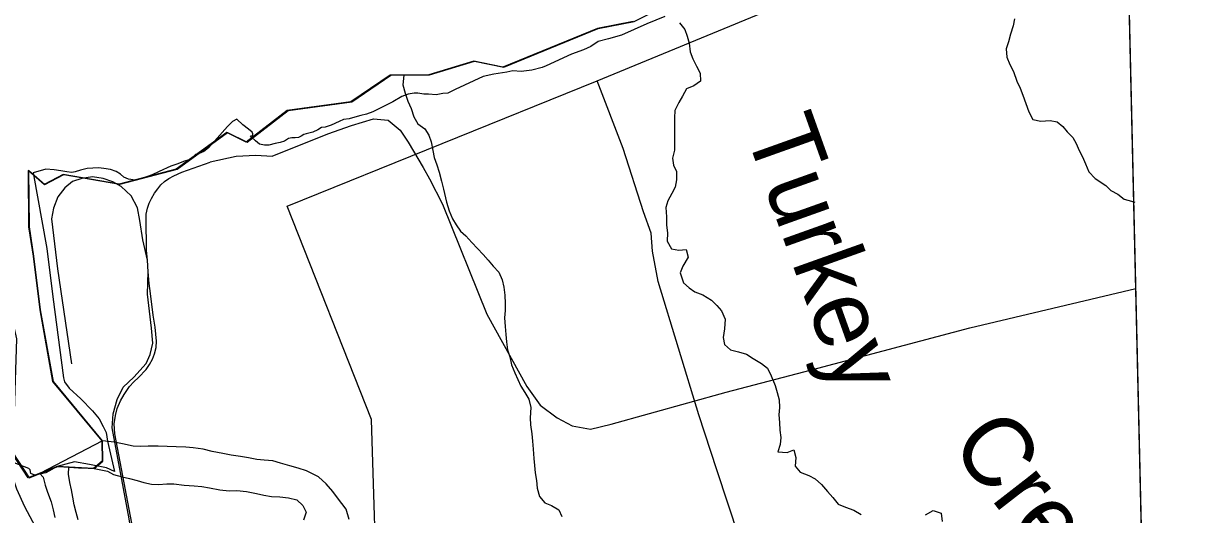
# Model space of a CAD drawing. Extents: x -5.4 to 71.3, y -12 to 22.
# Drawn here: x 5.375 to 6.976, y 17.692 to 18.359 of the extents above; entities that cross this region are included whole.
import ezdxf

# ---------------------------------------------------------------- set-up
doc = ezdxf.new("R2010")
doc.units = 0
for name, color, linetype in [('GM_X_City_Street', 7, 'Continuous'), ('GM_X_Major_Lake', 7, 'Continuous'), ('GM_X_Minor_River', 7, 'Continuous'), ('GM_X_Minor_River_Text', 7, 'Continuous'), ('GM_X_Rail_Line', 7, 'Continuous'), ('PM_X_Surveyed_Line', 7, 'Continuous'), ('SH_Cut_Line', 7, 'Continuous')]:
    doc.layers.add(name, color=color, linetype=linetype)

msp = doc.modelspace()

# ---------------------------------------------------------------- linework, layer by layer
at = {"layer": 'GM_X_City_Street'}
for points in [[(5.7326, 18.1109), (6.1537, 18.2812), (6.3856, 18.3767), (6.6338, 18.4748), (6.7914, 18.529), (6.8726, 18.5488)], [(6.407, 16.3093), (6.397, 16.5818), (6.3923, 16.6844), (6.3863, 16.833), (6.3845, 16.926), (6.3806, 16.9764), (6.3788, 17.0696), (6.3745, 17.1827), (6.3691, 17.2804), (6.3634, 17.4185), (6.3581, 17.5422), (6.3558, 17.6221), (6.3538, 17.6381), (6.3466, 17.6604), (6.3163, 17.7524), (6.2919, 17.8272), (6.2367, 18.0086), (6.229, 18.0496), (6.227, 18.0742), (6.2167, 18.1032), (6.1889, 18.1893), (6.1537, 18.2812)], [(5.5421, 16.1498), (5.5477, 16.1543), (5.554, 16.1621), (5.5621, 16.1924), (5.5656, 16.209), (5.5789, 16.3142), (5.6142, 16.5364), (5.631, 16.6494), (5.6428, 16.7087), (5.6642, 16.7534), (5.6824, 16.7855), (5.6905, 16.8061), (5.6947, 16.8366), (5.7054, 16.8663), (5.7632, 16.9149), (5.7916, 16.9498), (5.8275, 17.0254), (5.8434, 17.0875), (5.8273, 17.2232), (5.8383, 17.4603), (5.8525, 17.6491), (5.8512, 17.6897), (5.8472, 17.8207), (5.7326, 18.1109)]]:
    msp.add_lwpolyline(points, dxfattribs=at)
at = {"layer": 'GM_X_Major_Lake'}
for points in [[(6.1552, 18.3521), (6.2038, 18.3619), (6.2532, 18.3865), (6.3626, 18.4332), (6.4367, 18.4704), (6.5123, 18.506), (6.5777, 18.501), (6.6745, 18.5451), (6.7414, 18.5906), (6.8166, 18.6157)], [(5.3888, 18.0427), (5.3828, 18.0829), (5.3821, 18.1593), (5.4037, 18.1402), (5.4295, 18.1538), (5.5055, 18.1407), (5.5834, 18.1611), (5.6518, 18.2111), (5.6784, 18.1977), (5.7339, 18.2409), (5.8205, 18.2525), (5.8737, 18.2889), (5.9261, 18.2892), (5.9873, 18.3078), (6.0268, 18.2998), (6.1552, 18.3521)], [(5.289, 18.2544), (5.3008, 18.2556), (5.327, 18.1408), (5.3288, 18.0888), (5.3652, 17.9303), (5.3602, 17.7754), (5.3822, 17.7416), (5.4213, 17.7567), (5.4707, 17.7543), (5.4825, 17.7641), (5.4821, 17.7918), (5.4153, 17.8725), (5.3979, 17.9701), (5.3888, 18.0427)]]:
    msp.add_lwpolyline(points, dxfattribs=at)
at = {"layer": 'GM_X_Minor_River'}
msp.add_line((5.4821, 17.7918), (5.3969, 17.7473), dxfattribs=at)
for points in [[(6.7206, 18.3654), (6.7189, 18.3559), (6.7149, 18.3448), (6.7124, 18.3341), (6.7092, 18.3245), (6.7101, 18.3135), (6.7141, 18.3033), (6.7192, 18.2939), (6.7236, 18.2807), (6.728, 18.2713), (6.732, 18.2619), (6.736, 18.2505), (6.74, 18.2392), (6.7455, 18.2287), (6.7562, 18.2262), (6.7691, 18.2272), (6.7786, 18.2255), (6.786, 18.2192), (6.7922, 18.2117), (6.7995, 18.2043), (6.8042, 18.196), (6.8082, 18.1866), (6.8129, 18.1779), (6.8169, 18.1685), (6.8216, 18.1576), (6.8302, 18.1486), (6.8444, 18.139), (6.8514, 18.1323), (6.861, 18.1272), (6.8694, 18.1205), (6.8794, 18.1176), (6.8838, 18.1164)], [(6.2657, 18.3601), (6.273, 18.3511), (6.2759, 18.3417), (6.2787, 18.3326), (6.28, 18.3208), (6.2836, 18.311), (6.2888, 18.3012), (6.2935, 18.2918), (6.2941, 18.2805), (6.2851, 18.2746), (6.2752, 18.2702), (6.2697, 18.2602), (6.2646, 18.2518), (6.2594, 18.241), (6.2588, 18.2311), (6.2586, 18.2216), (6.2589, 18.2068), (6.2587, 18.1969), (6.2589, 18.1871), (6.256, 18.176), (6.2573, 18.1665), (6.2613, 18.1579), (6.2615, 18.1468), (6.2598, 18.1365), (6.255, 18.1281), (6.2495, 18.1181), (6.247, 18.1089), (6.2479, 18.0964), (6.2478, 18.085), (6.2491, 18.0744), (6.2489, 18.0634), (6.2548, 18.0529), (6.2647, 18.0511), (6.2746, 18.0517), (6.2774, 18.0415), (6.27, 18.0292), (6.2664, 18.02), (6.2712, 18.0064), (6.2786, 17.9997), (6.2863, 17.9942), (6.2973, 17.9902), (6.3089, 17.9832), (6.3162, 17.9757), (6.3225, 17.9683), (6.3276, 17.9573), (6.3267, 17.944), (6.325, 17.9322), (6.3267, 17.9228), (6.3348, 17.9153), (6.3459, 17.9129), (6.3566, 17.9096), (6.3658, 17.9037), (6.3769, 17.8971), (6.385, 17.8908), (6.3902, 17.8803), (6.3953, 17.8671), (6.3982, 17.8576), (6.401, 17.8474), (6.4012, 17.8372), (6.4006, 17.8273), (6.4012, 17.8166), (6.4017, 17.8064), (6.4031, 17.7965), (6.4021, 17.787), (6.3992, 17.7767), (6.4118, 17.7758), (6.4209, 17.7794), (6.4237, 17.7692), (6.4228, 17.7574), (6.4294, 17.7492), (6.4412, 17.7448), (6.4497, 17.74), (6.4586, 17.7326), (6.4667, 17.7229), (6.4737, 17.7147), (6.4811, 17.7057), (6.491, 17.7017), (6.5025, 17.6974), (6.5121, 17.6915)], [(5.891, 18.289), (5.89, 18.2759), (5.8929, 18.2645), (5.8965, 18.2536), (5.9013, 18.2434), (5.9049, 18.2321), (5.91, 18.2227), (5.9196, 18.216), (5.9251, 18.2074), (5.9283, 18.1983), (5.9304, 18.1866), (5.9325, 18.1771), (5.9361, 18.1669), (5.9393, 18.1571), (5.9422, 18.145), (5.945, 18.1337), (5.9491, 18.1163), (5.9528, 18.1046), (5.9572, 18.0936), (5.9622, 18.0854), (5.9681, 18.0767), (5.9754, 18.0704), (5.9836, 18.0614), (5.9913, 18.0532), (5.9991, 18.045), (6.0057, 18.0372), (6.0127, 18.0293), (6.0204, 18.0211), (6.0248, 18.0105), (6.0269, 18.0007), (6.0282, 17.9897), (6.0288, 17.9787), (6.0286, 17.9688), (6.028, 17.9589), (6.0286, 17.9472), (6.0295, 17.9365), (6.0308, 17.9263), (6.0322, 17.9157), (6.035, 17.9059), (6.0375, 17.8953), (6.0419, 17.8843), (6.0458, 17.8753), (6.0502, 17.8663), (6.0556, 17.8576), (6.0611, 17.8486), (6.0636, 17.8369), (6.0627, 17.8232), (6.0633, 17.8137), (6.065, 17.8012), (6.0659, 17.7913), (6.0669, 17.7807), (6.0679, 17.7678), (6.0688, 17.7583), (6.0697, 17.7481), (6.0715, 17.7379), (6.0724, 17.7273), (6.0753, 17.7163), (6.0826, 17.7077), (6.0918, 17.7037), (6.1018, 17.6978), (6.1058, 17.6891)], [(5.8169, 17.6847), (5.8129, 17.6987), (5.807, 17.7065), (5.8011, 17.7144), (5.7949, 17.723), (5.7856, 17.7335), (5.7755, 17.7428), (5.759, 17.7512), (5.7475, 17.7548), (5.7364, 17.7576), (5.7238, 17.7615), (5.7131, 17.7647), (5.7013, 17.7657), (5.6914, 17.7666), (5.6803, 17.7687), (5.6692, 17.7704), (5.6566, 17.7724), (5.6456, 17.7745), (5.6311, 17.7772), (5.6188, 17.7804), (5.6051, 17.7821), (5.5952, 17.783), (5.5819, 17.7835), (5.5697, 17.7841), (5.5575, 17.7846), (5.5438, 17.7847), (5.5332, 17.7841), (5.5237, 17.7847), (5.5092, 17.7879), (5.4977, 17.7899), (5.4821, 17.7918)], [(5.4376, 17.7353), (5.4358, 17.7466), (5.4364, 17.7559), (5.4495, 17.7552), (5.4645, 17.7546), (5.4707, 17.7543), (5.4886, 17.7507), (5.497, 17.7462), (5.5085, 17.743), (5.5188, 17.7406), (5.5292, 17.7377), (5.5383, 17.7352), (5.5483, 17.7331), (5.5582, 17.7326), (5.5692, 17.7335), (5.5787, 17.7333), (5.5928, 17.7317), (5.6065, 17.7308), (5.6168, 17.7295), (5.6275, 17.7278), (5.6412, 17.725), (5.6538, 17.7237), (5.6644, 17.7243), (5.6774, 17.723), (5.6911, 17.7203), (5.7011, 17.7178), (5.7117, 17.7161), (5.7228, 17.7155), (5.7346, 17.7142), (5.7461, 17.7114), (5.7542, 17.704), (5.7586, 17.695), (5.755, 17.6839)], [(5.3969, 17.7473), (5.4013, 17.7426), (5.4042, 17.7316), (5.4074, 17.7222), (5.4122, 17.709), (5.4151, 17.698), (5.4172, 17.6878)], [(5.4488, 17.6846), (5.446, 17.6944), (5.4435, 17.7046), (5.4418, 17.7152), (5.44, 17.7254), (5.4376, 17.7353)], [(6.5996, 17.6912), (6.6101, 17.6971), (6.6208, 17.6935), (6.6222, 17.6822)]]:
    msp.add_lwpolyline(points, dxfattribs=at)
at = {"layer": 'GM_X_Minor_River_Text'}
for points in [[(2.1, 14.1), (6.9755, 14.1), (6.9588, 14.9805), (6.9517, 15.3029), (6.9368, 15.8488), (6.9366, 15.8554), (6.9363, 15.8669), (6.9247, 16.3154), (6.8724, 18.5494)], [(6.2456, 18.3685), (6.2213, 18.3586), (6.1868, 18.3431), (6.169, 18.3384), (6.155, 18.3346), (6.1453, 18.328), (6.1352, 18.3231), (6.1187, 18.3175), (6.0845, 18.3017), (6.0789, 18.2991), (6.0651, 18.2958), (6.0506, 18.2938), (6.0391, 18.2948), (6.0309, 18.2928), (6.0135, 18.2902), (5.9988, 18.2871), (5.9609, 18.2692), (5.9509, 18.2646), (5.9442, 18.2641), (5.9353, 18.2622), (5.9246, 18.263), (5.9182, 18.2632), (5.9103, 18.2643), (5.9052, 18.2643), (5.8972, 18.2632), (5.8883, 18.2597), (5.8761, 18.2525), (5.8627, 18.2457), (5.8492, 18.2392), (5.8403, 18.236), (5.8327, 18.2341), (5.8247, 18.2318), (5.8171, 18.2295), (5.8091, 18.2285), (5.8033, 18.2257), (5.7923, 18.2209), (5.7842, 18.2183), (5.7795, 18.2176), (5.7744, 18.2147), (5.7676, 18.2115), (5.7586, 18.2092), (5.7555, 18.2082), (5.7517, 18.2058), (5.7482, 18.204), (5.7436, 18.2038), (5.7392, 18.2038), (5.7346, 18.2027), (5.729, 18.199), (5.7231, 18.1972), (5.7165, 18.1959), (5.7079, 18.1939), (5.7022, 18.1935), (5.6953, 18.1953), (5.6899, 18.1995), (5.6844, 18.2048), (5.6831, 18.2064), (5.6861, 18.2069), (5.6863, 18.2092), (5.6851, 18.2114), (5.6803, 18.2155), (5.6724, 18.2215), (5.6643, 18.2289), (5.6586, 18.2258), (5.6519, 18.219), (5.6376, 18.2032), (5.6261, 18.1903), (5.6197, 18.1851), (5.6133, 18.1824), (5.6083, 18.1809), (5.6043, 18.1764), (5.5992, 18.1738), (5.5932, 18.172), (5.5831, 18.1681), (5.5746, 18.1651), (5.559, 18.158), (5.5492, 18.1532), (5.5418, 18.1505), (5.5332, 18.1478), (5.5262, 18.1463), (5.5173, 18.1477), (5.5111, 18.1504), (5.5063, 18.1544), (5.5006, 18.158), (5.4929, 18.1606), (5.4839, 18.1621), (5.4764, 18.1627), (5.461, 18.1622), (5.4523, 18.1597), (5.4449, 18.1574), (5.4404, 18.1567), (5.4334, 18.1574), (5.4254, 18.1589), (5.4165, 18.1604), (5.4051, 18.1612), (5.3877, 18.1561), (5.4065, 18.0532), (5.4146, 17.9874), (5.4289, 17.8773), (5.4302, 17.8721), (5.4366, 17.8633), (5.4524, 17.8487), (5.4684, 17.8326), (5.4775, 17.8215), (5.483, 17.8114), (5.4869, 17.803), (5.4889, 17.7914), (5.4982, 17.7503), (5.4876, 17.7552), (5.4641, 17.7596), (5.4438, 17.7631), (5.4202, 17.7567), (5.4052, 17.7485), (5.39, 17.7453), (5.3848, 17.7474), (5.3837, 17.7523), (5.3818, 17.7542), (5.3619, 17.762)]]:
    msp.add_lwpolyline(points, dxfattribs=at)
at = {"layer": 'GM_X_Rail_Line'}
msp.add_line((5.5441, 18.0215), (5.5429, 18.0374), dxfattribs=at)
for points in [[(5.6281, 18.1712), (5.6634, 18.1786), (5.69, 18.1803), (5.7124, 18.1786), (5.788, 18.2092), (5.8201, 18.2204), (5.8498, 18.2293), (5.8699, 18.2277), (5.886, 18.214), (5.8972, 18.1979), (5.9173, 18.1634), (5.9262, 18.1481), (5.9438, 18.1135), (6.0041, 17.9641), (6.0582, 17.8658), (6.0763, 17.8404), (6.0993, 17.8229), (6.1196, 17.8124), (6.1447, 17.8076), (6.1728, 17.8146), (6.3291, 17.8581), (6.4533, 17.8907), (6.6598, 17.9452), (6.8853, 17.9988)], [(5.3035, 18.2153), (5.3553, 17.9524), (5.3595, 17.9285), (5.3615, 17.9129), (5.3603, 17.8742), (5.3571, 17.8173), (5.3558, 17.785), (5.3553, 17.766), (5.3578, 17.748), (5.365, 17.7265), (5.376, 17.7026), (5.3904, 17.6752), (5.3913, 17.6726)], [(5.5429, 18.0374), (5.5418, 18.0511), (5.5411, 18.0942), (5.5412, 18.0998), (5.5429, 18.1079), (5.5452, 18.1147), (5.5486, 18.1214), (5.5527, 18.1284), (5.557, 18.1344), (5.5612, 18.1398), (5.5664, 18.1444), (5.5721, 18.1483), (5.5787, 18.1521), (5.5898, 18.157), (5.6282, 18.1706), (5.6283, 18.1706)], [(5.5429, 18.0374), (5.5366, 18.0649), (5.5329, 18.0915), (5.5297, 18.1085), (5.5208, 18.125), (5.5075, 18.1376), (5.4961, 18.144), (5.4828, 18.1485), (5.4685, 18.1507), (5.454, 18.1485), (5.4412, 18.1445), (5.4308, 18.1359), (5.4214, 18.1233), (5.4153, 18.108), (5.4128, 18.0935), (5.4209, 18.0254), (5.4397, 17.8964)], [(5.5403, 17.5586), (5.5356, 17.5822), (5.5181, 17.6858), (5.4952, 17.8096), (5.4964, 17.8286), (5.5018, 17.8478), (5.5102, 17.8646), (5.5245, 17.8782), (5.5413, 17.8969), (5.5469, 17.9092), (5.5502, 17.9245), (5.5484, 17.9448), (5.5432, 17.9911), (5.5441, 18.0215)], [(5.5274, 17.6513), (5.4988, 17.8014), (5.4979, 17.8149), (5.4996, 17.8264), (5.502, 17.8358), (5.5062, 17.8462), (5.5113, 17.8549), (5.5149, 17.8604), (5.5188, 17.8657), (5.5246, 17.872), (5.531, 17.8781), (5.5413, 17.8888), (5.5459, 17.8954), (5.5499, 17.9027), (5.5528, 17.9102), (5.5548, 17.9189), (5.5552, 17.9274), (5.5545, 17.9366), (5.5534, 17.9463), (5.551, 17.9627), (5.5467, 17.9957), (5.5453, 18.0056), (5.5441, 18.0215)]]:
    msp.add_lwpolyline(points, dxfattribs=at)
at = {"layer": 'PM_X_Surveyed_Line'}
for points in [[(2.1, 14.1), (6.9757, 14.1), (6.955, 15.1854), (6.9275, 16.1897), (6.8702, 18.6385)], [(6.2027, 18.3619), (6.154, 18.3521), (6.0256, 18.2998), (5.9861, 18.3078), (5.925, 18.2893), (5.8725, 18.2889), (5.8193, 18.2526), (5.7327, 18.2409), (5.6772, 18.1977), (5.6507, 18.2111), (5.5822, 18.1611), (5.5044, 18.1407), (5.4284, 18.1538), (5.4026, 18.1402), (5.3809, 18.1593), (5.3816, 18.0829), (5.3877, 18.0427), (5.3968, 17.9701), (5.4142, 17.8725), (5.481, 17.7918), (5.4813, 17.7641), (5.4696, 17.7543), (5.4202, 17.7567), (5.381, 17.7416), (5.359, 17.7754)]]:
    msp.add_lwpolyline(points, dxfattribs=at)
at = {"layer": 'SH_Cut_Line'}
for points in [[(2.1, 14.1), (6.9755, 14.1), (6.9588, 14.9805), (6.9517, 15.3029), (6.9368, 15.8488), (6.9366, 15.8554), (6.9363, 15.8669), (6.9247, 16.3154), (6.8724, 18.5494)], [(6.2456, 18.3685), (6.2213, 18.3586), (6.1868, 18.3431), (6.169, 18.3384), (6.155, 18.3346), (6.1453, 18.328), (6.1352, 18.3231), (6.1187, 18.3175), (6.0845, 18.3017), (6.0789, 18.2991), (6.0651, 18.2958), (6.0506, 18.2938), (6.0391, 18.2948), (6.0309, 18.2928), (6.0135, 18.2902), (5.9988, 18.2871), (5.9609, 18.2692), (5.9509, 18.2646), (5.9442, 18.2641), (5.9353, 18.2622), (5.9246, 18.263), (5.9182, 18.2632), (5.9103, 18.2643), (5.9052, 18.2643), (5.8972, 18.2632), (5.8883, 18.2597), (5.8761, 18.2525), (5.8627, 18.2457), (5.8492, 18.2392), (5.8403, 18.236), (5.8327, 18.2341), (5.8247, 18.2318), (5.8171, 18.2295), (5.8091, 18.2285), (5.8033, 18.2257), (5.7923, 18.2209), (5.7842, 18.2183), (5.7795, 18.2176), (5.7744, 18.2147), (5.7676, 18.2115), (5.7586, 18.2092), (5.7555, 18.2082), (5.7517, 18.2058), (5.7482, 18.204), (5.7436, 18.2038), (5.7392, 18.2038), (5.7346, 18.2027), (5.729, 18.199), (5.7231, 18.1972), (5.7165, 18.1959), (5.7079, 18.1939), (5.7022, 18.1935), (5.6953, 18.1953), (5.6899, 18.1995), (5.6844, 18.2048), (5.6831, 18.2064), (5.6861, 18.2069), (5.6863, 18.2092), (5.6851, 18.2114), (5.6803, 18.2155), (5.6724, 18.2215), (5.6643, 18.2289), (5.6586, 18.2258), (5.6519, 18.219), (5.6376, 18.2032), (5.6261, 18.1903), (5.6197, 18.1851), (5.6133, 18.1824), (5.6083, 18.1809), (5.6043, 18.1764), (5.5992, 18.1738), (5.5932, 18.172), (5.5831, 18.1681), (5.5746, 18.1651), (5.559, 18.158), (5.5492, 18.1532), (5.5418, 18.1505), (5.5332, 18.1478), (5.5262, 18.1463), (5.5173, 18.1477), (5.5111, 18.1504), (5.5063, 18.1544), (5.5006, 18.158), (5.4929, 18.1606), (5.4839, 18.1621), (5.4764, 18.1627), (5.461, 18.1622), (5.4523, 18.1597), (5.4449, 18.1574), (5.4404, 18.1567), (5.4334, 18.1574), (5.4254, 18.1589), (5.4165, 18.1604), (5.4051, 18.1612), (5.3877, 18.1561), (5.4065, 18.0532), (5.4146, 17.9874), (5.4289, 17.8773), (5.4302, 17.8721), (5.4366, 17.8633), (5.4524, 17.8487), (5.4684, 17.8326), (5.4775, 17.8215), (5.483, 17.8114), (5.4869, 17.803), (5.4889, 17.7914), (5.4982, 17.7503), (5.4876, 17.7552), (5.4641, 17.7596), (5.4438, 17.7631), (5.4202, 17.7567), (5.4052, 17.7485), (5.39, 17.7453), (5.3848, 17.7474), (5.3837, 17.7523), (5.3818, 17.7542), (5.3619, 17.762)]]:
    msp.add_lwpolyline(points, dxfattribs=at)

# ---------------------------------------------------------------- texts
at = {"layer": 'GM_X_Minor_River_Text'}
for s, height, rotation, p in [('Turkey', 0.09474, 289.6535, (6.3537, 18.214)), ('Creek', 0.09475, 307.85, (6.6312, 17.7858))]:
    msp.add_text(s, height=height, rotation=rotation, dxfattribs=at).set_placement(p)

doc.saveas('drawing.dxf')
